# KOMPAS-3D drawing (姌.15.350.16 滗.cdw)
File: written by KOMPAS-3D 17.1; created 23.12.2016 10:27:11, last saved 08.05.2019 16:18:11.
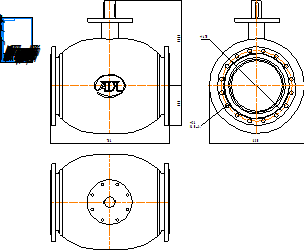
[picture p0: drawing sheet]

Sheet 1: A4, portrait

Title block, sheet 1: name: КШ.15.350.16 фф; material: Внимание! Данный продукт является объектом авторского права ООО «Торговый Дом АДЛ». / Запрещается изменение, копирование, распространение / (в том числе путем копирования на другие сайты и ресурсы в Интернете) / или любое иное использование информации и объектов без предварительного / согласия правообладателя (ООО «Торговый Дом АДЛ»).; sheets: 1; organisation: ООО "Торговый дом АДЛ"; sheet format: A4; stored path: C:\Users\tra\Desktop\2д чертежи\Шаровые краны БИВАЛ\КШ_Бивал_серия_14_15\KOMPAS_2D\КШ.15.350.16 фф.cdw

Views: Вид 1, Проекционный вид 3
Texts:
  Klimkovich
  ADL
Dimensions and other numbers on the sheet: 786; 564,5; 260; 470; 1:1; 1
